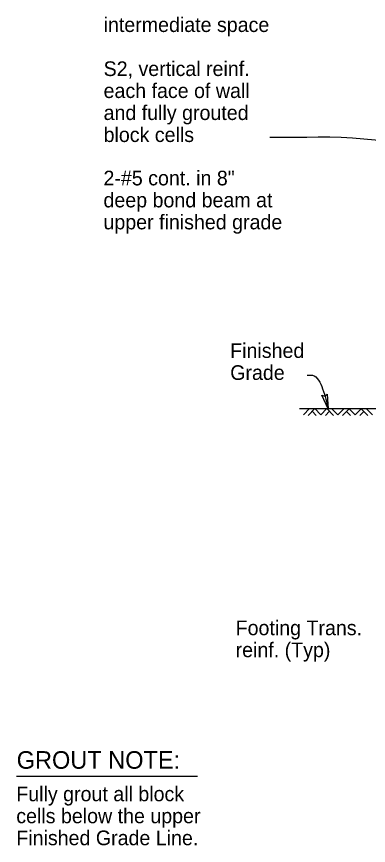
# Model space of a CAD drawing. Extents: x 0 to 2.83, y -0.03 to 1.83.
# Drawn here: x 0.939 to 1.251, y 0.687 to 1.423 of the extents above; entities that cross this region are included whole.
import ezdxf

# ---------------------------------------------------------------- set-up
doc = ezdxf.new("R2010")
doc.units = 0
for name, color, linetype in [('54', 7, 'Continuous'), ('55', 7, 'Continuous'), ('57', 7, 'Continuous'), ('58', 7, 'Continuous')]:
    doc.layers.add(name, color=color, linetype=linetype)

msp = doc.modelspace()

# ---------------------------------------------------------------- linework, layer by layer
at = {"layer": '54'}
msp.add_lwpolyline([(1.21583, 1.07459), (1.2101, 1.08649), (1.21279, 1.08567), (1.21475, 1.08761)], close=True, dxfattribs=at)
at = {"layer": '55'}
for p, q in [((1.17942, 1.31549), (1.16391, 1.31549)), ((1.19681, 1.31549), (1.17942, 1.31549))]:
    msp.add_line(p, q, dxfattribs=at)
msp.add_arc((1.20945, 0.90122), 0.41447, 69.37727, 91.7479, dxfattribs=at)
msp.add_spline([(1.19719, 1.10426), (1.20164, 1.10426), (1.21077, 1.09232), (1.21583, 1.07459)], degree=3, dxfattribs=at)
at = {"layer": '57'}
msp.add_line((0.9391, 0.74824), (1.09982, 0.74824), dxfattribs=at)
at = {"layer": '58'}
for p, q in [((1.19032, 1.07472), (1.48181, 1.07472)), ((1.19919, 1.07463), (1.19381, 1.06924)), ((1.20378, 1.07463), (1.19783, 1.06868)), ((1.20378, 1.07463), (1.20917, 1.06924)), ((1.21456, 1.07463), (1.20917, 1.06924)), ((1.21456, 1.07463), (1.22051, 1.06868)), ((1.21892, 1.0745), (1.22431, 1.06911)), ((1.2297, 1.0745), (1.22431, 1.06911)), ((1.23429, 1.0745), (1.22834, 1.06855)), ((1.23429, 1.0745), (1.23967, 1.06911)), ((1.24506, 1.0745), (1.23967, 1.06911)), ((1.24506, 1.0745), (1.25101, 1.06855)), ((1.24965, 1.0745), (1.25504, 1.06911)), ((1.20146, 1.07236), (1.20514, 1.06868)), ((1.21688, 1.07236), (1.21319, 1.06868)), ((1.23196, 1.07223), (1.23565, 1.06855)), ((1.24739, 1.07223), (1.2437, 1.06855))]:
    msp.add_line(p, q, dxfattribs=at)

# ---------------------------------------------------------------- texts
at = {"layer": '57'}
for s, height, p in [('intermediate space', 0.0130167, (1.01636, 1.409)), ('S2, vertical reinf. ', 0.0130167, (1.01634, 1.36992)), ('each face of wall ', 0.0130167, (1.01634, 1.3504)), ('and fully grouted ', 0.0130167, (1.01634, 1.33087)), ('block cells', 0.0130167, (1.01634, 1.31135)), ('2-#5 cont. in 8"', 0.0130167, (1.01624, 1.27285)), ('deep bond beam at', 0.0130167, (1.01624, 1.25332)), ('upper finished grade', 0.0130167, (1.01624, 1.2338)), ('Finished', 0.013017, (1.12872, 1.11967)), ('Grade', 0.013017, (1.12872, 1.10014)), ('Footing Trans.', 0.0130167, (1.13354, 0.87352)), ('reinf. (Typ)', 0.0130167, (1.13354, 0.854)), ('GROUT NOTE:', 0.015625, (0.9392, 0.75493)), ('Fully grout all block', 0.0130167, (0.93884, 0.72611)), ('cells below the upper ', 0.0130167, (0.93884, 0.70658)), ('Finished Grade Line.', 0.0130167, (0.93884, 0.68706))]:
    msp.add_text(s, height=height, dxfattribs=at).set_placement(p)

doc.saveas('drawing.dxf')
